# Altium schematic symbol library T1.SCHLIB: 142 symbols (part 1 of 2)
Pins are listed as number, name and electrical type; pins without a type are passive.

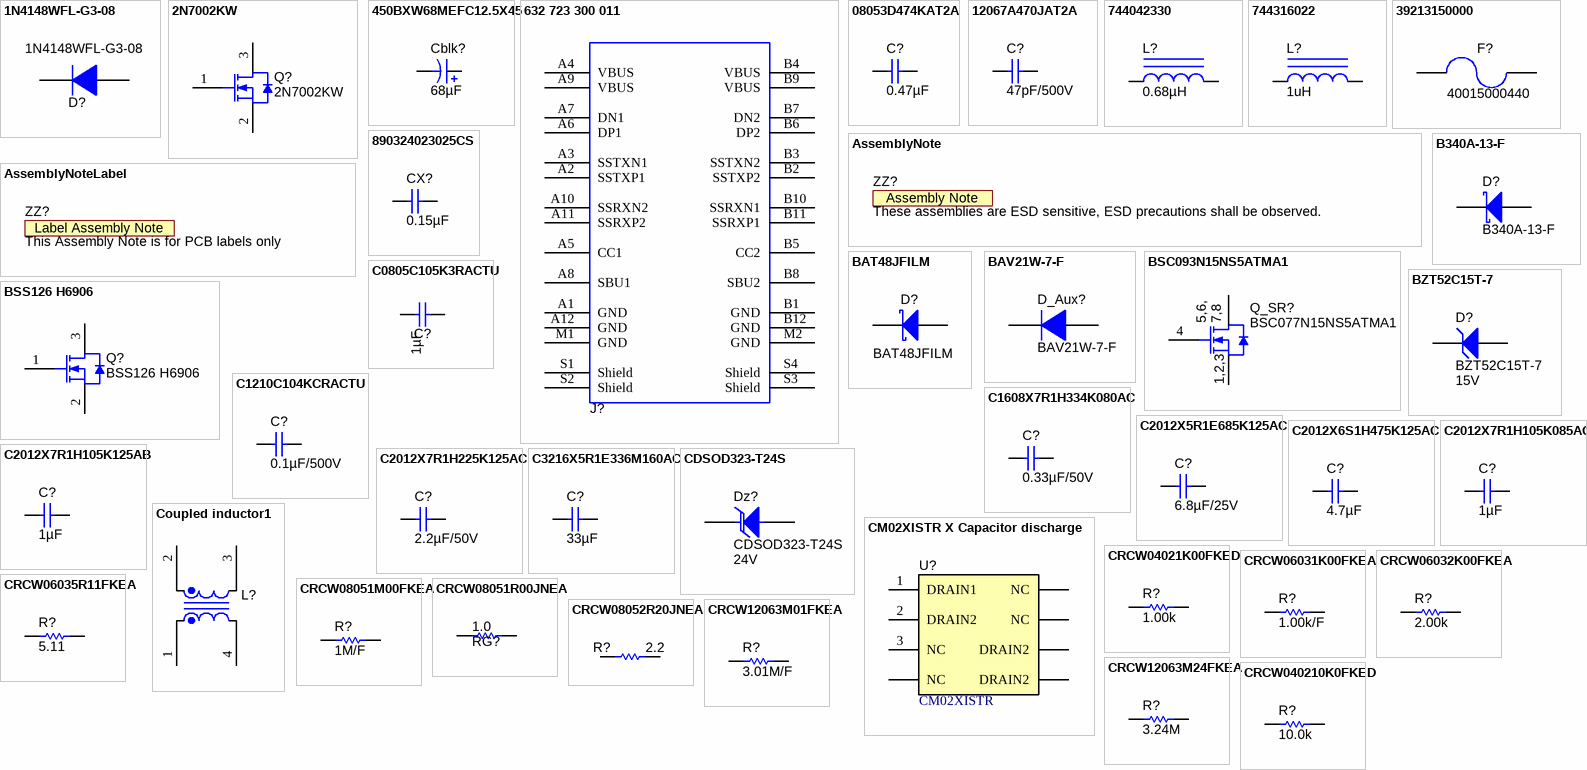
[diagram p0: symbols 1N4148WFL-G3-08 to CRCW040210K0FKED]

## 1N4148WFL-G3-08
designator D?
Diode, Switching, 100 V, 0.15 A, SOD-123FL; Manufacturer: Vishay-Semiconductor; U/M: EA; Vf_V: 1.2; Value: 100V; Value1: 0.15A; Value2: 1.2V; Io_A: 0.15; Vr_V: 100; TJmax_C: 150; SizeAreaWB_mm2: 12.19; SizeArea_mm2: 5.94; SizeX_mm: 3.6; SizeY_mm: 1.65; SizeZ_mm: 0.98; AEC Category: Q101
signal-integrity model Diode
footprint SOD-123FL
pins: 1 K, 2 A

## 2N7002KW
designator Q?
MOSFET, N-CH, 60 V, 0.31 A, SOT-323; Manufacturer: Fairchild Semiconductor; Alternate Manufacturer: None; U/M: EA; ChType: N; Value: 60V; VdsMax_V: 60; Value1: 1.6 ohm; Rdson45_ohm: 1.6; Value2: ? nC; Vgs_V: 2.1; IdsMax_A: 0.31; SizeAreaWB_mm2: 10.24; SizeArea_mm2: 4.84; SizeX_mm: 2.2; SizeZ_mm: 1.1; AEC Category: Q101
footprint SOT-323
pins: 1 G, 2 S, 3 D

## 450BXW68MEFC12.5X45
designator Cblk?  ValueDisplayed: 68µF  (hidden comment: 450BXW68MEFC12.5X45)
CAP, AL, 68 µF, 450 V, +/- 20%, TH; Manufacturer: Rubycon; Polarized: Y; CompType: Capacitor; Value: 68uF; U/M: EA; Cap_F: 0.000068; Tolerance_%: 20; Value1: Unknown; VDC_V: 450; Value2: 450V; IRMS_A: 0.61; TaMin_C: -40; TaMax_C: 105; Cap_Case: 12.5X45mm; SizeAreaWB_mm2: 210.25; SizeArea_mm2: 156.25; SizeX_mm: 12.5; SizeZ_mm: 47; AEC Category: Q200; AEC Qualified: N
signal-integrity model Cap
simulation model Cap
footprint BXW_1250x4500
footprint BXW_1250x4500_Horizontal_UP
footprint BXW_1250x4500_Horizontal_DOWN
pins: 1 +, 2 -

## 632 723 300 011
designator J?  (value not drawn)
Connector, Receptacle, USB Type C, R/A; Manufacturer: Wurth Elektronik; SymbolCreator: a0412235; Gender: Female; ContactFinish: Gold; Current_A: 3; Voltage_V: 5; Cert_UL: Y
footprint Wurth_632_723_300_011
pins: A1 GND, A2 SSTXP1, A3 SSTXN1, A4 VBUS, A5 CC1, A6 DP1, A7 DN1, A8 SBU1, A9 VBUS, A10 SSRXN2, A11 SSRXP2, A12 GND, B1 GND, B2 SSTXP2, B3 SSTXN2, B4 VBUS, B5 CC2, B6 DP2, B7 DN2, B8 SBU2, B9 VBUS, B10 SSRXN1, B11 SSRXP1, B12 GND, M1 GND, M2 GND, S1 Shield, S2 Shield, S3 Shield, S4 Shield

## 08053D474KAT2A
designator C?  ValueDisplayed: 0.47µF  (hidden comment: 08053D474KAT2A)
CAP, CERM, 0.47 µF, 25 V,+/- 10%, X5R, 0805; Manufacturer: AVX; Polarized: N; CompType: Capacitor; Value: 0.47uF; U/M: EA; Cap_F: 0.00000047; Tolerance_%: 10; ESR_ohm: 0.017; Value1: 0.017 ohm; VDC_V: 25; Value2: 25V; TaMin_C: -55; TaMax_C: 85; Cap_Case: 0805; SizeArea_mm2: 2.5; SizeAreaWB_mm2: 6.75; SizeX_mm: 2; SizeY_mm: 1.25; SizeZ_mm: 1.45; AEC Category: Q200; Green_Lifecycle: Active; Green_REACh: Passed
signal-integrity model Cap
simulation model Cap
footprint 0805_HV
footprint 0805_HV1
footprint 0805
footprint 0805M
footprint 0805L
pins: 1, 2

## 12067A470JAT2A
designator C?  ValueDisplayed: 47pF/500V  (hidden comment: 12067A470JAT2A)
CAP, CERM, 47 pF, 500 V, +/- 5%, C0G/NP0, 1206; Manufacturer: AVX; Polarized: N; CompType: Capacitor; Value: 47pF; U/M: EA; Cap_F: 0.000000000047; Tolerance_%: 5; Value1: Unknown; VDC_V: 500; Value2: 500V; TaMin_C: -55; TaMax_C: 125; Cap_Case: 1206; SizeArea_mm2: 5.12; SizeAreaWB_mm2: 10.92; SizeX_mm: 3.2; SizeY_mm: 1.6; SizeZ_mm: 1.35; AEC Category: Q200
signal-integrity model Cap
simulation model Cap
footprint 1206
footprint 1206M
footprint 1206L
pins: 1, 2

## 744042330
designator L?  ValueDisplayed: 0.68µH  (hidden comment: 744042330)
Inductor, Shielded Drum Core, Metal Composite, 33 µH, 0.5 A, 0.382 ohm, SMD; Manufacturer: Wurth Elektronik; Value: 0.68uH; Ind_H: 33.0E-6; Imax_A: 0.5; Irms: 0.72A @ 30C rise; Isat: 0.5A @ 35% inductance drop; DCR_ohm: 0.382; Value2: 0.5A; SizeAreaWB_mm2: 33.64; SizeArea_mm2: 23.04; SizeX_mm: 4.8; SizeZ_mm: 2; AEC Category: Q200
signal-integrity model Inductor
simulation model Inductor
footprint 1206L (1206 from SM-752 data)
pins: 1, 2

## 744316022
designator L?  ValueDisplayed: 1uH  (hidden comment: 744316022)
FIXED IND 1UH 11.5A 4.75 MOHM; Manufacturer: Wurth Elektronik; CompType: Inductor; Value: 220nH; Ind_H: 220.0E-9; Imax_A: 20; Irms: 20A @ 40C rise; Isat: 25A @ 30% inductance drop; DCR_ohm: 0.00125; Value1: 0.00125 ohm; Value2: 20A; SizeAreaWB_mm2: 55.48; SizeArea_mm2: 29.68; SizeX_mm: 5.6; SizeY_mm: 5.3; SizeZ_mm: 4.3; AEC Category: Q200; AEC Qualified: N
signal-integrity model Inductor
simulation model Inductor
footprint WE-HCI_5040
pins: 1, 2

## 39213150000
designator F?, comment 40015000440
Fuse, 5 A, 250VAC/VDC, TH; Manufacturer: Littelfuse; VDC_V: 250; Irating_A: 5; Green_Lifecycle: Active; Green_REACh: Passed
footprint FUSE_392
pins: 1, 2

## 890324023025CS
designator CX?  ValueDisplayed: 0.15µF  (hidden comment: 890324023025CS)
CAP, Film, 0.15 µF,  V, +/- 10%, TH; Manufacturer: Wurth Elektronik; Polarized: N; CompType: Capacitor; Value: 0.15uF; U/M: EA; Cap_F: 0.00000015; Tolerance_%: 10; Value1: Unknown; TaMin_C: -40; TaMax_C: 105; Cap_Case: 13x7x12; SizeAreaWB_mm2: 135; SizeArea_mm2: 91; SizeX_mm: 13; SizeY_mm: 7; SizeZ_mm: 12.5; AEC Category: Q200
signal-integrity model Cap
simulation model Cap
footprint WCAP-FTX2_1300x700x1200
pins: 1, 2

## AssemblyNote
designator ZZ?, comment These assemblies are ESD sensitive, ESD precautions shall be observed.  (no BOM)
SymbolCreator: codlsc; CompType: AssemblyNote
footprint AssemblyNote

## AssemblyNoteLabel
designator ZZ?, comment This Assembly Note is for PCB labels only  (no BOM)
SymbolCreator: a0412235
footprint AssemblyNoteLabel

## B340A-13-F
designator D?
Diode, Schottky, 40 V, 3 A, SMA; Manufacturer: Diodes Inc.; U/M: EA; Vf_V: 0.5; Value: 40V; Value1: 3A; Value2: 0.5V; Io_A: 3; Vr_V: 40; TJmax_C: 125; RJC_CperW: 25; SizeAreaWB_mm2: 37.3428; SizeArea_mm2: 16.3228; SizeX_mm: 5.59; SizeY_mm: 2.92; SizeZ_mm: 2.87; AEC Category: Q101
signal-integrity model Diode
simulation model DI_B340A
footprint SMA
pins: 1 K, 2 A

## BAT48JFILM
designator D?
Diode, Schottky, 30 V, 0.35 A, SOD-323; Manufacturer: STMicroelectronics; U/M: EA; Vf_V: 0.75; Value: 30V; Value1: 0.35A; Value2: 0.75V; Io_A: 0.35; Vr_V: 30; TJmax_C: 150; SizeAreaWB_mm2: 8.695; SizeArea_mm2: 3.645; SizeX_mm: 2.7; SizeY_mm: 1.35; SizeZ_mm: 1; AEC Category: Q101
signal-integrity model Diode
footprint SOD-323
pins: 1 K, 2 A

## BAV21W-7-F
designator D_Aux?
Diode, Switching, 200 V, 0.2 A, SOD-123; Manufacturer: Diodes Inc.; U/M: EA; Vf_V: 1.25; Value: 200V; Value1: 0.2A; Value2: 1.25V; Io_A: 0.2; Vr_V: 200; TJmax_C: 150; SizeAreaWB_mm2: 13.095; SizeArea_mm2: 6.545; SizeX_mm: 3.85; SizeY_mm: 1.7; SizeZ_mm: 1.35; AEC Category: Q101
signal-integrity model Diode
simulation model DI_BAV21W
footprint SOD-123
pins: 1 K, 2 A

## BSC093N15NS5ATMA1
designator Q_SR?, comment BSC077N15NS5ATMA1
MOSFET, N-CH, 150 V, 87 A, PG-TDSON-8; Manufacturer: Infineon Technologies; Alternate Manufacturer: None; U/M: EA; ChType: N; Value: 150V; VdsMax_V: 150; Value1: ? ohm; Value2: 33 nC; QgTyp_nC: 33; Vgs_V: 20; IdsMax_A: 87; SizeAreaWB_mm2: 55.131; SizeArea_mm2: 29.351; SizeX_mm: 5.99; SizeY_mm: 4.9; SizeZ_mm: 1.12; AEC Category: Q101
footprint PG-TDSON-8
pins: 1 S, 2 S, 3 S, 4 G, 5 D, 6 D, 7 D, 8 D, 9 D

## BSS126 H6906
designator Q?
MOSFET, N-CH, 600 V, 0.021 A, AEC-Q101, SOT-23; Manufacturer: Infineon Technologies; Alternate Manufacturer: None; U/M: EA; ChType: N; Value: 600V; VdsMax_V: 600; Value1: ? ohm; Value2: 1.4 nC; QgTyp_nC: 1.4; Vgs_V: 20; IdsMax_A: 0.021; SizeAreaWB_mm2: 14; SizeArea_mm2: 7.5; SizeX_mm: 2.5; SizeY_mm: 3; SizeZ_mm: 1.1; AEC Category: Q101; AEC Qualified: Y
footprint SOT-23
footprint SOT-23M
footprint SOT-23L
pins: 1 G, 2 S, 3 D

## BZT52C15T-7
designator D?  value 15V
Diode, Zener, 15 V, 300 mW, SOD-523; Manufacturer: Diodes Inc.; SymbolCreator: a0412235; U/M: EA; Power_W: 0.3; Vz_V: 15; Value1: 0.3W; RJA_CperW: 417; SizeAreaWB_mm2: 5.13; SizeArea_mm2: 1.53; SizeX_mm: 1.7; SizeY_mm: 0.9; SizeZ_mm: 0.65; AEC Category: Q101
signal-integrity model Diode
footprint SOD-523
pins: 1 K, 2 A

## C0805C105K3RACTU
designator C?  ValueDisplayed: 1µF  (hidden comment: C0805C105K3RACTU)
CAP, CERM, 1 µF, 25 V, +/- 10%, X7R, 0805; Manufacturer: Kemet; Polarized: N; CompType: Capacitor; Value: 1uF; U/M: EA; Cap_F: 0.000001; Tolerance_%: 10; Value1: Unknown; VDC_V: 25; Value2: 25V; TaMin_C: -55; TaMax_C: 125; Cap_Case: 0805; SizeArea_mm2: 2.5; SizeAreaWB_mm2: 6.75; SizeX_mm: 2; SizeY_mm: 1.25; SizeZ_mm: 1.45; AEC Category: Q200
signal-integrity model Cap
simulation model Cap
footprint 0805_HV
footprint 0805_HV1
footprint 0805
footprint 0805M
footprint 0805L
pins: 1, 2

## C1210C104KCRACTU
designator C?  ValueDisplayed: 0.1µF/500V  (hidden comment: C1210C104KCRACTU)
CAP, CERM, 0.1 µF, 500 V, +/- 10%, X7R, 1210; Manufacturer: Kemet; Polarized: N; CompType: Capacitor; Value: 0.1uF; U/M: EA; Cap_F: 0.0000001; Tolerance_%: 10; Value1: Unknown; VDC_V: 500; Value2: 500V; TaMin_C: -55; TaMax_C: 125; Cap_Case: 1210; SizeArea_mm2: 8; SizeAreaWB_mm2: 14.7; SizeX_mm: 3.2; SizeY_mm: 2.5; SizeZ_mm: 2.3; AEC Category: Q200
signal-integrity model Cap
simulation model Cap
footprint 1210_230
footprint 1210_230M
footprint 1210_230L
pins: 1, 2

## C1608X7R1H334K080AC
designator C?  ValueDisplayed: 0.33µF/50V  (hidden comment: C1608X7R1H334K080AC)
CAP, CERM, 0.33 µF, 50 V, +/- 10%, X7R, 0603; Manufacturer: TDK; Polarized: N; CompType: Capacitor; Value: 0.33uF; U/M: EA; Cap_F: 0.00000033; Tolerance_%: 10; ESR_ohm: 0.016574; Value1: 0.016574 ohm; VDC_V: 50; Value2: 50V; IRMS_A: 1.28367; TaMin_C: -55; TaMax_C: 125; Cap_Case: 0603; SizeArea_mm2: 1.28; SizeAreaWB_mm2: 4.68; SizeX_mm: 1.6; SizeY_mm: 0.8; SizeZ_mm: 1; AEC Category: Q200
signal-integrity model Cap
simulation model Cap
footprint 0603
footprint 0603M
footprint 0603L
footprint 0603_HV
footprint 0603S
pins: 1, 2

## C2012X5R1E685K125AC
designator C?  ValueDisplayed: 6.8µF/25V  (hidden comment: C2012X5R1E685K125AC)
CAP, CERM, 6.8 µF, 25 V, +/- 10%, X5R, 0805; Manufacturer: TDK; Polarized: N; CompType: Capacitor; Value: 6.8uF; U/M: EA; Cap_F: 0.0000068; Tolerance_%: 10; Value1: Unknown; VDC_V: 25; Value2: 25V; TaMin_C: -55; TaMax_C: 85; Cap_Case: 0805; SizeArea_mm2: 2.5; SizeAreaWB_mm2: 6.75; SizeX_mm: 2; SizeY_mm: 1.25; SizeZ_mm: 1.45; AEC Category: Q200
signal-integrity model Cap
simulation model Cap
footprint 0805_HV
footprint 0805_HV1
footprint 0805
footprint 0805M
footprint 0805L
pins: 1, 2

## C2012X6S1H475K125AC
designator C?  ValueDisplayed: 4.7µF  (hidden comment: C2012X6S1H475K125AC)
CAP, CERM, 4.7 µF, 50 V, +/- 10%, X6S, 0805; Manufacturer: TDK; Polarized: N; CompType: Capacitor; Value: 4.7uF; U/M: EA; Cap_F: 0.0000047; Tolerance_%: 10; ESR_ohm: 0.002346; Value1: 0.002346 ohm; VDC_V: 50; Value2: 50V; IRMS_A: 4.26021; TaMin_C: -55; TaMax_C: 105; Cap_Case: 0805; SizeArea_mm2: 2.5; SizeAreaWB_mm2: 6.75; SizeX_mm: 2; SizeY_mm: 1.25; SizeZ_mm: 1.45; AEC Category: Q200
signal-integrity model Cap
simulation model Cap
footprint 0805_HV
footprint 0805_HV1
footprint 0805
footprint 0805M
footprint 0805L
pins: 1, 2

## C2012X7R1H105K085AC
designator C?  ValueDisplayed: 1µF  (hidden comment: C2012X7R1H105K085AC)
CAP, CERM, 1 µF, 50 V, +/- 10%, X7R, 0805; Manufacturer: TDK; Polarized: N; CompType: Capacitor; Value: 1uF; U/M: EA; Cap_F: 0.000001; Tolerance_%: 10; Value1: Unknown; VDC_V: 50; Value2: 50V; TaMin_C: -55; TaMax_C: 125; Cap_Case: 0805; SizeArea_mm2: 2.5; SizeAreaWB_mm2: 6.75; SizeX_mm: 2; SizeY_mm: 1.25; SizeZ_mm: 1.45; AEC Category: Q200
signal-integrity model Cap
simulation model Cap
footprint 0805_HV
footprint 0805_HV1
footprint 0805
footprint 0805M
footprint 0805L
pins: 1, 2

## C2012X7R1H105K125AB
designator C?  ValueDisplayed: 1µF  (hidden comment: C2012X7R1H105K125AB)
CAP, CERM, 1 µF, 50 V, +/- 10%, X7R, 0805; Manufacturer: TDK; Polarized: N; CompType: Capacitor; Value: 1uF; U/M: EA; Cap_F: 0.000001; Tolerance_%: 10; ESR_ohm: 0.008782; Value1: 0.008782 ohm; VDC_V: 50; Value2: 50V; IRMS_A: 2.20488; TaMin_C: -55; TaMax_C: 125; Cap_Case: 0805; SizeArea_mm2: 2.5; SizeAreaWB_mm2: 6.75; SizeX_mm: 2; SizeY_mm: 1.25; SizeZ_mm: 1.45; AEC Category: Q200
signal-integrity model Cap
simulation model Cap
footprint 0805_HV
footprint 0805_HV1
footprint 0805
footprint 0805M
footprint 0805L
pins: 1, 2

## C2012X7R1H225K125AC
designator C?  ValueDisplayed: 2.2µF/50V  (hidden comment: C2012X7R1H225K125AC)
CAP, CERM, 2.2 µF, 50 V, +/- 10%, X7R, 0805; Manufacturer: TDK; Polarized: N; CompType: Capacitor; Value: 2.2uF; U/M: EA; Cap_F: 0.0000022; Tolerance_%: 10; ESR_ohm: 0.00366; Value1: 0.00366 ohm; VDC_V: 50; Value2: 50V; IRMS_A: 3.41207; TaMin_C: -55; TaMax_C: 125; Cap_Case: 0805; SizeArea_mm2: 2.5; SizeAreaWB_mm2: 6.75; SizeX_mm: 2; SizeY_mm: 1.25; SizeZ_mm: 1.45; AEC Category: Q200
signal-integrity model Cap
simulation model Cap
footprint 0805_HV
footprint 0805_HV1
footprint 0805
footprint 0805M
footprint 0805L
pins: 1, 2

## C3216X5R1E336M160AC
designator C?  ValueDisplayed: 33µF  (hidden comment: C3216X5R1E336M160AC)
CAP, CERM, 33 µF, 25 V, +/- 20%, X5R, 1206; Manufacturer: TDK; Polarized: N; CompType: Capacitor; Value: 33uF; U/M: EA; Cap_F: 0.000033; Tolerance_%: 20; ESR_ohm: 0.002648; Value1: 0.002648 ohm; VDC_V: 25; Value2: 25V; IRMS_A: 4.45864; TaMin_C: -55; TaMax_C: 85; Cap_Case: 1206_180; SizeArea_mm2: 5.12; SizeAreaWB_mm2: 10.92; SizeX_mm: 3.2; SizeY_mm: 1.6; SizeZ_mm: 1.8; AEC Category: Q200
signal-integrity model Cap
simulation model Cap
footprint 1206_180
footprint 1206_180M
footprint 1206_180L
pins: 1, 2

## CDSOD323-T24S
designator Dz?  value 24V
Diode, TVS, Uni, 24 V, 49 Vc, SOD-323; Manufacturer: Bourns; U/M: EA; Vr_V: 24; Value1: W; SizeAreaWB_mm2: 8.695; SizeArea_mm2: 3.645; SizeX_mm: 2.7; SizeY_mm: 1.35; SizeZ_mm: 1; AEC Category: Q101; AEC Qualified: N
footprint SOD-323
pins: 1 K, 2 A

## CM02XISTR X Capacitor discharge
designator U?, comment CM02XISTR
1.25 V, 50 ppm / degC, 50 uA Series (Bandgap) Voltage Reference, -40 to 125 degC, 3-pin SOT-23 (DBZ), Green (RoHS & no Sb/Br); Manufacturer: Champion; Alternate Manufacturer: Texas Instruments; Alternate PartNumber: Equivalent; Initial Accuracy @ 25/deg C(%): 0.2; Iq(Max)(uA): 50; Rating: Catalog; SubFamily: Series Voltage Reference; Temp Coeff(Typ)(ppm/ degree C): 20; VI(Max)(V): 5.5; VI(Min)(V): 1.8; VO(V): 1.25
footprint SOP8 (SOIC, 8-Leads, Body 4.9x3.9mm, Pitch 1.27mm, IPC Medium Density)
pins: 1 DRAIN1 (power), 2 DRAIN2 (power), 3 NC (power), 4 NC, 5 DRAIN2, 6 DRAIN2, 7 NC, 8 NC

## Coupled inductor1
designator L?, comment 7448011305  (value not drawn)
Coupled inductor, 5 mH, 1.3 A, 0.2 ohm, TH; Manufacturer: Wurth Elektronik; SymbolCreator: a0799628; Value: 5mH; Ind_H: 5.0E-3; DCR_ohm: 0.2
footprint WE-CMBNC_XS (TH, 4-Leads, Body 14x7.5mm)
pins: 1, 2, 3, 4
1 alternate drawing of the same symbol

## CRCW04021K00FKED
designator R?  ValueDisplayed: 1.00k  (hidden comment: CRCW04021K00FKED)
RES, 1.00 k, 1%, 0.063 W, 0402; Manufacturer: Vishay-Dale; CompType: Resistor; Value: 1.00k; Res_ohm: 1000; Value_Code: 1k00; Tolerance_%: 1; Power_W: 0.063; Value2: 0.063W; VDC_V: 50; TempCo: 100 ppm/C; SizeArea_mm2: 0.5; SizeZ_mm: 0.6; EIA_Code: E96; U/M: EA; AEC Category: Q200
signal-integrity model Resistor
simulation model Resistor
footprint 0402
footprint 0402M
footprint 0402L
footprint 0402S
pins: 1, 2

## CRCW06031K00FKEA
designator R?  ValueDisplayed: 1.00k/F  (hidden comment: CRCW06031K00FKEA)
RES, 1.00 k, 1%, 0.1 W, 0603; Manufacturer: Vishay-Dale; CompType: Resistor; Value: 1.00k; Res_ohm: 1000; Value_Code: 1k00; Tolerance_%: 1; Power_W: 0.1; Value2: 0.1W; VDC_V: 75; TempCo: 100 ppm/C; SizeArea_mm2: 1.28; SizeX_mm: 1.6; SizeY_mm: 0.8; EIA_Code: E96; U/M: EA; AEC Category: Q200
signal-integrity model Resistor
simulation model Resistor
footprint 0603
footprint 0603M
footprint 0603L
footprint 0603_HV
footprint 0603S
pins: 1, 2

## CRCW06032K00FKEA
designator R?  ValueDisplayed: 2.00k  (hidden comment: CRCW06032K00FKEA)
RES, 2.00 k, 1%, 0.1 W, 0603; Manufacturer: Vishay-Dale; CompType: Resistor; Value: 2.00k; Res_ohm: 2000; Value_Code: 2k00; Tolerance_%: 1; Power_W: 0.1; Value2: 0.1W; VDC_V: 75; TempCo: 100 ppm/C; SizeArea_mm2: 1.28; SizeX_mm: 1.6; SizeY_mm: 0.8; EIA_Code: E96; U/M: EA; AEC Category: Q200
signal-integrity model Resistor
simulation model Resistor
footprint 0603
footprint 0603M
footprint 0603L
footprint 0603_HV
footprint 0603S
pins: 1, 2

## CRCW06035R11FKEA
designator R?  ValueDisplayed: 5.11  (hidden comment: CRCW06035R11FKEA)
RES, 5.11, 1%, 0.1 W, 0603; Manufacturer: Vishay-Dale; CompType: Resistor; Value: 5.11; Value_Code: 5R11; Tolerance_%: 1; Power_W: 0.1; Value2: 0.1W; VDC_V: 75; TempCo: 100 ppm/C; SizeArea_mm2: 1.28; SizeX_mm: 1.6; SizeY_mm: 0.8; EIA_Code: E96; U/M: EA; AEC Category: Q200
signal-integrity model Resistor
simulation model Resistor
footprint 0603
footprint 0603M
footprint 0603L
footprint 0603_HV
footprint 0603S
pins: 1, 2

## CRCW08051M00FKEA
designator R?  ValueDisplayed: 1M/F  (hidden comment: CRCW08051M00FKEA)
RES, 1.00 M, 1%, 0.125 W, 0805; Manufacturer: Vishay-Dale; CompType: Resistor; Value: 1.00Meg; Res_ohm: 1000000; Value_Code: 1M00; Tolerance_%: 1; Power_W: 0.125; Value2: 0.125W; VDC_V: 150; TempCo: 100 ppm/C; SizeArea_mm2: 2.5; SizeX_mm: 2; SizeY_mm: 1.25; SizeZ_mm: 1.45; EIA_Code: E96; U/M: EA; AEC Category: Q200
signal-integrity model Resistor
simulation model Resistor
footprint 0805_HV
footprint 0805_HV1
footprint 0805
footprint 0805M
footprint 0805L
pins: 1, 2

## CRCW08051R00JNEA
designator RG?  ValueDisplayed: 1.0  (hidden comment: CRCW08051R00JNEA)
RES, 1.0, 5%, 0.125 W, 0805; Manufacturer: Vishay-Dale; CompType: Resistor; Value: 1.0; Res_ohm: 1; Value_Code: 1R00; Tolerance_%: 5; Power_W: 0.125; Value2: 0.125W; VDC_V: 150; TempCo: 200 ppm/C; SizeArea_mm2: 2.5; SizeX_mm: 2; SizeY_mm: 1.25; SizeZ_mm: 1.45; EIA_Code: E24; U/M: EA; AEC Category: Q200
signal-integrity model Resistor
simulation model Resistor
footprint 0805_HV
footprint 0805_HV1
footprint 0805
footprint 0805M
footprint 0805L
pins: 1, 2

## CRCW08052R20JNEA
designator R?  ValueDisplayed: 2.2  (hidden comment: CRCW08052R20JNEA)
RES, 2.2, 5%, 0.125 W, 0805; Manufacturer: Vishay-Dale; CompType: Resistor; Value: 2.2; Value_Code: 2R20; Tolerance_%: 5; Power_W: 0.125; Value2: 0.125W; VDC_V: 150; TempCo: 200 ppm/C; SizeArea_mm2: 2.5; SizeX_mm: 2; SizeY_mm: 1.25; SizeZ_mm: 1.45; EIA_Code: E24; U/M: EA; AEC Category: Q200; Green_Lifecycle: Active; Green_REACh: Passed
signal-integrity model Resistor
simulation model Resistor
footprint 0805_HV
footprint 0805_HV1
footprint 0805
footprint 0805M
footprint 0805L
pins: 1, 2

## CRCW12063M01FKEA
designator R?  ValueDisplayed: 3.01M/F  (hidden comment: CRCW12063M01FKEA)
RES, 3.01 M, 1%, 0.25 W, 1206; Manufacturer: Vishay-Dale; CompType: Resistor; Value: 3.01Meg; Res_ohm: 3010000; Value_Code: 3M01; Tolerance_%: 1; Power_W: 0.25; Value2: 0.25W; VDC_V: 200; TempCo: 100 ppm/C; SizeArea_mm2: 5.12; SizeX_mm: 3.2; SizeY_mm: 1.6; SizeZ_mm: 1.35; EIA_Code: E96; U/M: EA; AEC Category: Q200
signal-integrity model Resistor
simulation model Resistor
footprint 1206
footprint 1206M
footprint 1206L
pins: 1, 2

## CRCW12063M24FKEA
designator R?  ValueDisplayed: 3.24M  (hidden comment: CRCW12063M24FKEA)
RES, 3.24 M, 1%, 0.25 W, 1206; Manufacturer: Vishay-Dale; CompType: Resistor; Value: 3.24Meg; Res_ohm: 3240000; Value_Code: 3M24; Tolerance_%: 1; Power_W: 0.25; Value2: 0.25W; VDC_V: 200; TempCo: 100 ppm/C; SizeArea_mm2: 5.12; SizeX_mm: 3.2; SizeY_mm: 1.6; SizeZ_mm: 1.35; EIA_Code: E96; U/M: EA; AEC Category: Q200
signal-integrity model Resistor
simulation model Resistor
footprint 1206
footprint 1206M
footprint 1206L
pins: 1, 2

## CRCW040210K0FKED
designator R?  ValueDisplayed: 10.0k  (hidden comment: CRCW040210K0FKED)
RES, 10.0 k, 1%, 0.063 W, 0402; Manufacturer: Vishay-Dale; CompType: Resistor; Value: 10.0k; Res_ohm: 10000; Value_Code: 10k0; Tolerance_%: 1; Power_W: 0.063; Value2: 0.063W; VDC_V: 50; TempCo: 100 ppm/C; SizeArea_mm2: 0.5; SizeZ_mm: 0.6; EIA_Code: E96; U/M: EA; AEC Category: Q200
signal-integrity model Resistor
simulation model Resistor
footprint 0402
footprint 0402M
footprint 0402L
footprint 0402S
pins: 1, 2

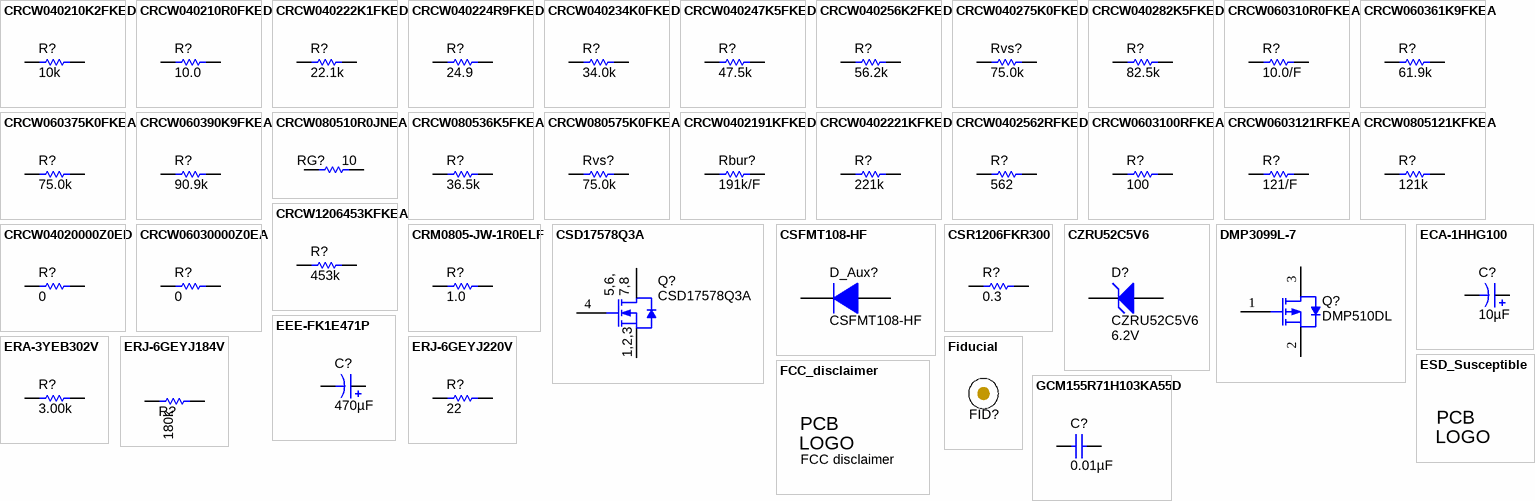
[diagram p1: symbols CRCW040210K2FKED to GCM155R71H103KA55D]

## CRCW040210K2FKED
designator R?  ValueDisplayed: 10k  (hidden comment: CRCW040210K2FKED)
RES, 10 k, 1%, 0.063 W, 0402; Manufacturer: Vishay-Dale; CompType: Resistor; Value: 10k; Res_ohm: 10200; Tolerance_%: 1; Power_W: 0.063; Value2: 0.063W; VDC_V: 50; TempCo: 100 ppm/C; SizeArea_mm2: 0.5; SizeZ_mm: 0.6; EIA_Code: E96; U/M: EA; AEC Category: Q200
signal-integrity model Resistor
simulation model Resistor
footprint 0402
footprint 0402M
footprint 0402L
footprint 0402S
pins: 1, 2

## CRCW040210R0FKED
designator R?  ValueDisplayed: 10.0  (hidden comment: CRCW040210R0FKED)
RES, 10.0, 1%, 0.063 W, 0402; Manufacturer: Vishay-Dale; CompType: Resistor; Value: 10.0; Res_ohm: 10; Value_Code: 10R0; Tolerance_%: 1; Power_W: 0.063; Value2: 0.063W; VDC_V: 50; TempCo: 100 ppm/C; SizeArea_mm2: 0.5; SizeZ_mm: 0.6; EIA_Code: E96; U/M: EA; AEC Category: Q200
signal-integrity model Resistor
simulation model Resistor
footprint 0402
footprint 0402M
footprint 0402L
footprint 0402S
pins: 1, 2

## CRCW040222K1FKED
designator R?  ValueDisplayed: 22.1k  (hidden comment: CRCW040222K1FKED)
RES, 22.1 k, 1%, 0.063 W, 0402; Manufacturer: Vishay-Dale; CompType: Resistor; Value: 22.1k; Res_ohm: 22100; Value_Code: 22k1; Tolerance_%: 1; Power_W: 0.063; Value2: 0.063W; VDC_V: 50; TempCo: 100 ppm/C; SizeArea_mm2: 0.5; SizeZ_mm: 0.6; EIA_Code: E96; U/M: EA; AEC Category: Q200
signal-integrity model Resistor
simulation model Resistor
footprint 0402
footprint 0402M
footprint 0402L
footprint 0402S
pins: 1, 2

## CRCW040224R9FKED
designator R?  ValueDisplayed: 24.9  (hidden comment: CRCW040224R9FKED)
RES, 24.9, 1%, 0.063 W, 0402; Manufacturer: Vishay-Dale; CompType: Resistor; Value: 24.9; Value_Code: 24R9; Tolerance_%: 1; Power_W: 0.063; Value2: 0.063W; VDC_V: 50; TempCo: 100 ppm/C; SizeArea_mm2: 0.5; SizeZ_mm: 0.6; EIA_Code: E96; U/M: EA; AEC Category: Q200
signal-integrity model Resistor
simulation model Resistor
footprint 0402
footprint 0402M
footprint 0402L
footprint 0402S
pins: 1, 2

## CRCW040234K0FKED
designator R?  ValueDisplayed: 34.0k  (hidden comment: CRCW040234K0FKED)
RES, 34.0 k, 1%, 0.063 W, 0402; Manufacturer: Vishay-Dale; CompType: Resistor; Value: 34.0k; Res_ohm: 34000; Value_Code: 34k0; Tolerance_%: 1; Power_W: 0.063; Value2: 0.063W; VDC_V: 50; TempCo: 100 ppm/C; SizeArea_mm2: 0.5; SizeZ_mm: 0.6; EIA_Code: E96; U/M: EA; AEC Category: Q200
signal-integrity model Resistor
simulation model Resistor
footprint 0402
footprint 0402M
footprint 0402L
footprint 0402S
pins: 1, 2

## CRCW040247K5FKED
designator R?  ValueDisplayed: 47.5k  (hidden comment: CRCW040247K5FKED)
RES, 47.5 k, 1%, 0.063 W, 0402; Manufacturer: Vishay-Dale; CompType: Resistor; Value: 47.5k; Res_ohm: 47500; Value_Code: 47k5; Tolerance_%: 1; Power_W: 0.063; Value2: 0.063W; VDC_V: 50; TempCo: 100 ppm/C; SizeArea_mm2: 0.5; SizeZ_mm: 0.6; EIA_Code: E96; U/M: EA; AEC Category: Q200
signal-integrity model Resistor
simulation model Resistor
footprint 0402
footprint 0402M
footprint 0402L
footprint 0402S
pins: 1, 2

## CRCW040256K2FKED
designator R?  ValueDisplayed: 56.2k  (hidden comment: CRCW040256K2FKED)
RES, 56.2 k, 1%, 0.063 W, 0402; Manufacturer: Vishay-Dale; CompType: Resistor; Value: 56.2k; Res_ohm: 56200; Value_Code: 56k2; Tolerance_%: 1; Power_W: 0.063; Value2: 0.063W; VDC_V: 50; TempCo: 100 ppm/C; SizeArea_mm2: 0.5; SizeZ_mm: 0.6; EIA_Code: E96; U/M: EA; AEC Category: Q200
signal-integrity model Resistor
simulation model Resistor
footprint 0402
footprint 0402M
footprint 0402L
footprint 0402S
pins: 1, 2

## CRCW040275K0FKED
designator Rvs?  ValueDisplayed: 75.0k  (hidden comment: CRCW040275K0FKED)
RES, 75.0 k, 1%, 0.063 W, 0402; Manufacturer: Vishay-Dale; CompType: Resistor; Value: 75.0k; Res_ohm: 75000; Value_Code: 75k0; Tolerance_%: 1; Power_W: 0.063; Value2: 0.063W; VDC_V: 50; TempCo: 100 ppm/C; SizeArea_mm2: 0.5; SizeZ_mm: 0.6; EIA_Code: E96; U/M: EA; AEC Category: Q200
signal-integrity model Resistor
simulation model Resistor
footprint 0402
footprint 0402M
footprint 0402L
footprint 0402S
pins: 1, 2

## CRCW040282K5FKED
designator R?  ValueDisplayed: 82.5k  (hidden comment: CRCW040282K5FKED)
RES, 82.5 k, 1%, 0.063 W, 0402; Manufacturer: Vishay-Dale; CompType: Resistor; Value: 82.5k; Res_ohm: 82500; Value_Code: 82k5; Tolerance_%: 1; Power_W: 0.063; Value2: 0.063W; VDC_V: 50; TempCo: 100 ppm/C; SizeArea_mm2: 0.5; SizeZ_mm: 0.6; EIA_Code: E96; U/M: EA; AEC Category: Q200
signal-integrity model Resistor
simulation model Resistor
footprint 0402
footprint 0402M
footprint 0402L
footprint 0402S
pins: 1, 2

## CRCW060310R0FKEA
designator R?  ValueDisplayed: 10.0/F  (hidden comment: CRCW060310R0FKEA)
RES, 10.0, 1%, 0.1 W, 0603; Manufacturer: Vishay-Dale; CompType: Resistor; Value: 10.0; Res_ohm: 10; Value_Code: 10R0; Tolerance_%: 1; Power_W: 0.1; Value2: 0.1W; VDC_V: 75; TempCo: 100 ppm/C; SizeArea_mm2: 1.28; SizeX_mm: 1.6; SizeY_mm: 0.8; EIA_Code: E96; U/M: EA; AEC Category: Q200
signal-integrity model Resistor
simulation model Resistor
footprint 0603
footprint 0603M
footprint 0603L
footprint 0603_HV
footprint 0603S
pins: 1, 2

## CRCW060361K9FKEA
designator R?  ValueDisplayed: 61.9k  (hidden comment: CRCW060361K9FKEA)
RES, 61.9 k, 1%, 0.1 W, 0603; Manufacturer: Vishay-Dale; CompType: Resistor; Value: 61.9k; Res_ohm: 61900; Value_Code: 61k9; Tolerance_%: 1; Power_W: 0.1; Value2: 0.1W; VDC_V: 75; TempCo: 100 ppm/C; SizeArea_mm2: 1.28; SizeX_mm: 1.6; SizeY_mm: 0.8; EIA_Code: E96; U/M: EA; AEC Category: Q200; Green_Lifecycle: Active; Green_REACh: Passed
signal-integrity model Resistor
simulation model Resistor
footprint 0603 (0603 from SM-752 data)
footprint 0603M
footprint 0603L
footprint 0603_HV
footprint 0603S
pins: 1, 2

## CRCW060375K0FKEA
designator R?  ValueDisplayed: 75.0k  (hidden comment: CRCW060375K0FKEA)
RES, 75.0 k, 1%, 0.1 W, 0603; Manufacturer: Vishay-Dale; CompType: Resistor; Value: 75.0k; Res_ohm: 75000; Value_Code: 75k0; Tolerance_%: 1; Power_W: 0.1; Value2: 0.1W; VDC_V: 75; TempCo: 100 ppm/C; SizeArea_mm2: 1.28; SizeX_mm: 1.6; SizeY_mm: 0.8; EIA_Code: E96; U/M: EA; AEC Category: Q200
signal-integrity model Resistor
simulation model Resistor
footprint 0603
footprint 0603M
footprint 0603L
footprint 0603_HV
footprint 0603S
pins: 1, 2

## CRCW060390K9FKEA
designator R?  ValueDisplayed: 90.9k  (hidden comment: CRCW060390K9FKEA)
RES, 90.9 k, 1%, 0.1 W, 0603; Manufacturer: Vishay-Dale; CompType: Resistor; Value: 90.9k; Res_ohm: 90900; Value_Code: 90k9; Tolerance_%: 1; Power_W: 0.1; Value2: 0.1W; VDC_V: 75; TempCo: 100 ppm/C; SizeArea_mm2: 1.28; SizeX_mm: 1.6; SizeY_mm: 0.8; EIA_Code: E96; U/M: EA; AEC Category: Q200
signal-integrity model Resistor
simulation model Resistor
footprint 0603
footprint 0603M
footprint 0603L
footprint 0603_HV
footprint 0603S
pins: 1, 2

## CRCW080510R0JNEA
designator RG?  ValueDisplayed: 10  (hidden comment: CRCW080510R0JNEA)
RES, 10, 5%, 0.125 W, 0805; Manufacturer: Vishay-Dale; CompType: Resistor; Value: 10; Value_Code: 10R0; Tolerance_%: 5; Power_W: 0.125; Value2: 0.125W; VDC_V: 150; TempCo: 200 ppm/C; SizeArea_mm2: 2.5; SizeX_mm: 2; SizeY_mm: 1.25; SizeZ_mm: 1.45; EIA_Code: E24; U/M: EA; AEC Category: Q200
signal-integrity model Resistor
simulation model Resistor
footprint 0805_HV
footprint 0805_HV1
footprint 0805
footprint 0805M
footprint 0805L
pins: 1, 2

## CRCW080536K5FKEA
designator R?  ValueDisplayed: 36.5k  (hidden comment: CRCW080536K5FKEA)
RES, 36.5 k, 1%, 0.125 W, 0805; Manufacturer: Vishay-Dale; CompType: Resistor; Value: 36.5k; Res_ohm: 36500; Value_Code: 36k5; Tolerance_%: 1; Power_W: 0.125; Value2: 0.125W; VDC_V: 150; TempCo: 100 ppm/C; SizeArea_mm2: 2.5; SizeX_mm: 2; SizeY_mm: 1.25; SizeZ_mm: 1.45; EIA_Code: E96; U/M: EA; AEC Category: Q200; Green_Lifecycle: Active; Green_REACh: Passed
signal-integrity model Resistor
simulation model Resistor
footprint 0805_HV
footprint 0805_HV1
footprint 0805
footprint 0805M
footprint 0805L
pins: 1, 2

## CRCW080575K0FKEA
designator Rvs?  ValueDisplayed: 75.0k  (hidden comment: CRCW080575K0FKEA)
RES, 75.0 k, 1%, 0.125 W, 0805; Manufacturer: Vishay-Dale; CompType: Resistor; Value: 75.0k; Res_ohm: 75000; Value_Code: 75k0; Tolerance_%: 1; Power_W: 0.125; Value2: 0.125W; VDC_V: 150; TempCo: 100 ppm/C; SizeArea_mm2: 2.5; SizeX_mm: 2; SizeY_mm: 1.25; SizeZ_mm: 1.45; EIA_Code: E96; U/M: EA; AEC Category: Q200
signal-integrity model Resistor
simulation model Resistor
footprint 0805_HV
footprint 0805_HV1
footprint 0805
footprint 0805M
footprint 0805L
pins: 1, 2

## CRCW0402191KFKED
designator Rbur?  ValueDisplayed: 191k/F  (hidden comment: CRCW0402191KFKED)
RES, 191 k, 1%, 0.063 W, 0402; Manufacturer: Vishay-Dale; CompType: Resistor; Value: 191k; Res_ohm: 191000; Tolerance_%: 1; Power_W: 0.063; Value2: 0.063W; VDC_V: 50; TempCo: 100 ppm/C; SizeArea_mm2: 0.5; SizeZ_mm: 0.6; EIA_Code: E96; U/M: EA; AEC Category: Q200
signal-integrity model Resistor
simulation model Resistor
footprint 0402
footprint 0402M
footprint 0402L
footprint 0402S
pins: 1, 2

## CRCW0402221KFKED
designator R?  ValueDisplayed: 221k  (hidden comment: CRCW0402221KFKED)
RES, 221 k, 1%, 0.063 W, 0402; Manufacturer: Vishay-Dale; CompType: Resistor; Value: 221k; Res_ohm: 221000; Tolerance_%: 1; Power_W: 0.063; Value2: 0.063W; VDC_V: 50; TempCo: 100 ppm/C; SizeArea_mm2: 0.5; SizeZ_mm: 0.6; EIA_Code: E96; U/M: EA; AEC Category: Q200
signal-integrity model Resistor
simulation model Resistor
footprint 0402
footprint 0402M
footprint 0402L
footprint 0402S
pins: 1, 2

## CRCW0402562RFKED
designator R?  ValueDisplayed: 562  (hidden comment: CRCW0402562RFKED)
RES, 562, 1%, 0.063 W, 0402; Manufacturer: Vishay-Dale; CompType: Resistor; Value: 562; Value_Code: 562R; Tolerance_%: 1; Power_W: 0.063; Value2: 0.063W; VDC_V: 50; TempCo: 100 ppm/C; SizeArea_mm2: 0.5; SizeZ_mm: 0.6; EIA_Code: E96; U/M: EA; AEC Category: Q200
signal-integrity model Resistor
simulation model Resistor
footprint 0402
footprint 0402M
footprint 0402L
footprint 0402S
pins: 1, 2

## CRCW0603100RFKEA
designator R?  ValueDisplayed: 100  (hidden comment: CRCW0603100RFKEA)
RES, 100, 1%, 0.1 W, 0603; Manufacturer: Vishay-Dale; CompType: Resistor; Value: 100; Value_Code: 100R; Tolerance_%: 1; Power_W: 0.1; Value2: 0.1W; VDC_V: 75; TempCo: 100 ppm/C; SizeArea_mm2: 1.28; SizeX_mm: 1.6; SizeY_mm: 0.8; EIA_Code: E96; U/M: EA; AEC Category: Q200
signal-integrity model Resistor
simulation model Resistor
footprint 0603
footprint 0603M
footprint 0603L
footprint 0603_HV
footprint 0603S
pins: 1, 2

## CRCW0603121RFKEA
designator R?  ValueDisplayed: 121/F  (hidden comment: CRCW0603121RFKEA)
RES, 121, 1%, 0.1 W, 0603; Manufacturer: Vishay-Dale; CompType: Resistor; Value: 121; Value_Code: 121R; Tolerance_%: 1; Power_W: 0.1; Value2: 0.1W; VDC_V: 75; TempCo: 100 ppm/C; SizeArea_mm2: 1.28; SizeX_mm: 1.6; SizeY_mm: 0.8; EIA_Code: E96; U/M: EA; AEC Category: Q200
signal-integrity model Resistor
simulation model Resistor
footprint 0603
footprint 0603M
footprint 0603L
footprint 0603_HV
footprint 0603S
pins: 1, 2

## CRCW0805121KFKEA
designator R?  ValueDisplayed: 121k  (hidden comment: CRCW0805121KFKEA)
RES, 121 k, 1%, 0.125 W, 0805; Manufacturer: Vishay-Dale; CompType: Resistor; Value: 121k; Res_ohm: 121000; Tolerance_%: 1; Power_W: 0.125; Value2: 0.125W; VDC_V: 150; TempCo: 100 ppm/C; SizeArea_mm2: 2.5; SizeX_mm: 2; SizeY_mm: 1.25; SizeZ_mm: 1.45; EIA_Code: E96; U/M: EA; AEC Category: Q200; Green_Lifecycle: Active; Green_REACh: Passed
signal-integrity model Resistor
simulation model Resistor
footprint 0805_HV
footprint 0805_HV1
footprint 0805
footprint 0805M
footprint 0805L
pins: 1, 2

## CRCW1206453KFKEA
designator R?  ValueDisplayed: 453k  (hidden comment: CRCW1206453KFKEA)
RES, 453 k, 1%, 0.25 W, 1206; Manufacturer: Vishay-Dale; CompType: Resistor; Value: 453k; Res_ohm: 453000; Tolerance_%: 1; Power_W: 0.25; Value2: 0.25W; VDC_V: 200; TempCo: 100 ppm/C; SizeArea_mm2: 5.12; SizeX_mm: 3.2; SizeY_mm: 1.6; SizeZ_mm: 1.35; EIA_Code: E96; U/M: EA; AEC Category: Q200
signal-integrity model Resistor
simulation model Resistor
footprint 1206
footprint 1206M
footprint 1206L
pins: 1, 2

## CRCW04020000Z0ED
designator R?  ValueDisplayed: 0  (hidden comment: CRCW04020000Z0ED)
RES, 0, 5%, 0.063 W, 0402; Manufacturer: Vishay-Dale; CompType: Resistor; Value: 0; Value_Code: 0000; Tolerance_%: 5; Power_W: 0.063; Value2: 0.063W; VDC_V: 50; TempCo: 200 ppm/C; SizeArea_mm2: 0.5; SizeX_mm: 1; SizeZ_mm: 0.6; EIA_Code: E24; U/M: EA; AEC Category: Q200
signal-integrity model Resistor
simulation model Resistor
footprint 0402
footprint 0402M
footprint 0402L
footprint 0402S
pins: 1, 2

## CRCW06030000Z0EA
designator R?  ValueDisplayed: 0  (hidden comment: CRCW06030000Z0EA)
RES, 0, 5%, 0.1 W, 0603; Manufacturer: Vishay-Dale; CompType: Resistor; Value: 0; Value_Code: 0000; Tolerance_%: 5; Power_W: 0.1; Value2: 0.1W; VDC_V: 75; TempCo: 200 ppm/C; SizeArea_mm2: 1.28; SizeX_mm: 1.6; SizeY_mm: 0.8; SizeZ_mm: 1; EIA_Code: E24; U/M: EA; AEC Category: Q200
signal-integrity model Resistor
simulation model Resistor
footprint 0603
footprint 0603M
footprint 0603L
footprint 0603_HV
footprint 0603S
pins: 1, 2

## CRM0805-JW-1R0ELF
designator R?  ValueDisplayed: 1.0  (hidden comment: CRM0805-JW-1R0ELF)
RES, 1.0, 5%, 0.25 W, 0805; Manufacturer: Bourns; CompType: Resistor; Value: 1.0; Res_ohm: 1; Value_Code: 1R00; Tolerance_%: 5; Power_W: 0.25; Value2: 0.25W; VDC_V: 0; TempCo: 100 ppm/C; SizeArea_mm2: 2.5; SizeX_mm: 2; SizeY_mm: 1.25; SizeZ_mm: 1.45; EIA_Code: E24; U/M: EA; AEC Category: Q200
signal-integrity model Resistor
simulation model Resistor
footprint 0805_HV
footprint 0805_HV1
footprint 0805
footprint 0805M
footprint 0805L
pins: 1, 2

## CSD17578Q3A
designator Q?
MOSFET, N-CH, 30 V, 14 A, DNH0008A (VSONP-8); Manufacturer: Texas Instruments; Alternate Manufacturer: None; U/M: EA; ChType: N; Value: 30V; VdsMax_V: 30; Value1: 0.0082 ohm; Rdson45_ohm: 0.0082; Value2: 7.9 nC; QgTyp_nC: 7.9; Vgs_V: 20; IdsMax_A: 14; SizeAreaWB_mm2: 18.49; SizeArea_mm2: 10.89; SizeX_mm: 3.3; SizeZ_mm: 0.9; AEC Category: Q101
footprint DNH0008A
footprint DNH0008A_NV
pins: 1 S, 2 S, 3 S, 4 G, 5 D, 6 D, 7 D, 8 D, 9 D

## CSFMT108-HF
designator D_Aux?
Diode, Superfast Rectifier, 600 V, 1 A, 3.5x1.6mm; Manufacturer: Comchip Technology; U/M: EA; Vf_V: 1.7; Value: 600V; Value1: 1A; Value2: 1.7V; Io_A: 1; Vr_V: 600; TJmax_C: 150; SizeAreaWB_mm2: 11.7; SizeArea_mm2: 5.6; SizeX_mm: 3.5; SizeY_mm: 1.6; AEC Category: Q101; AEC Qualified: N
signal-integrity model Diode
footprint SOD-123H
pins: 1 K, 2 A

## CSR1206FKR300
designator R?  ValueDisplayed: 0.3  (hidden comment: CSR1206FKR300)
RES, 0.3, 1%, 0.5 W, 1206; Manufacturer: Stackpole Electronics Inc; CompType: Resistor; Value: 0.3; Tolerance_%: 1; Value2: 0.5W; TempCo: 100 ppm/C; SizeArea_mm2: 5.12; SizeX_mm: 3.2; SizeY_mm: 1.6; SizeZ_mm: 1.35; U/M: EA; AEC Category: Q200; Value_Code: R300; Power_W: 0.5; EIA_Code: E96
signal-integrity model Resistor
simulation model Resistor
footprint 1206
footprint 1206M
footprint 1206L
pins: 1, 2

## CZRU52C5V6
designator D?  value 6.2V
Diode, Zener, 5.6 V, 150 mW, SOD-523F; Manufacturer: Comchip Technology; SymbolCreator: a0412235; U/M: EA; Power_W: 0.15; Vz_V: 5.6; Value1: 0.15W; SizeAreaWB_mm2: 5.13; SizeArea_mm2: 1.53; SizeX_mm: 1.7; SizeY_mm: 0.9; SizeZ_mm: 0.85; AEC Category: Q101
signal-integrity model Diode
footprint SOD-523F
pins: 1 K, 2 A

## DMP3099L-7
designator Q?, comment DMP510DL
MOSFET, P-CH, -30 V, -3.8 A, AEC-Q101, SOT-23; PartNumber: DMP3099L-7; Manufacturer: Diodes Inc.; Alternate Manufacturer: None; U/M: EA; ChType: P; Value: -30V; Value1: ? ohm; Value2: 5.2 nC; QgTyp_nC: 5.2; Vgs_V: -20; SizeAreaWB_mm2: 14; SizeArea_mm2: 7.5; SizeX_mm: 2.5; SizeY_mm: 3; SizeZ_mm: 1.1; AEC Category: Q101; AEC Qualified: Y
footprint SOT-23
footprint SOT-23M
footprint SOT-23L
pins: 1 G, 2 S, 3 D

## ECA-1HHG100
designator C?  ValueDisplayed: 10µF  (hidden comment: ECA-1HHG100)
CAP, AL, 10 µF, 50 V, +/- 20%, TH; Manufacturer: Panasonic; Polarized: Y; CompType: Capacitor; Value: 10uF; U/M: EA; Cap_F: 0.00001; Tolerance_%: 20; Value1: Unknown; VDC_V: 50; Value2: 50V; IRMS_A: 0.039; TaMin_C: -55; TaMax_C: 105; Cap_Case: 5x11mm; SizeArea_mm2: 25; SizeAreaWB_mm2: 49; SizeX_mm: 5; SizeZ_mm: 12; AEC Category: Q200; AEC Qualified: N
signal-integrity model Cap
simulation model Cap
footprint NHG_500x1100
pins: 1 +, 2 -

## EEE-FK1E471P
designator C?  ValueDisplayed: 470µF  (hidden comment: EEE-FK1E471P)
CAP, AL, 470 µF, 25 V, +/- 20%, 0.08 ohm, AEC-Q200 Grade 2, SMD; Manufacturer: Panasonic; Polarized: Y; CompType: Capacitor; Value: 470uF; U/M: EA; Cap_F: 0.00047; Tolerance_%: 20; VDC_V: 25; Value2: 25V; ESR_ohm: 0.08; IRMS_A: 0.85; TaMin_C: -55; TaMax_C: 105; Cap_Case: G; SizeAreaWB_mm2: 172.2; SizeArea_mm2: 123.6; SizeX_mm: 12; SizeY_mm: 10.3; SizeZ_mm: 10.2; AEC Category: Q200; AEC Grade: 2
signal-integrity model Cap
simulation model Cap
footprint SM_RADIAL_G
pins: 1 +, 2 -

## ERA-3YEB302V
designator R?  ValueDisplayed: 3.00k  (hidden comment: ERA-3YEB302V)
RES, 3.00 k, 0.1%, 0.1 W, 0603; Manufacturer: Panasonic; CompType: Resistor; Value: 3.00k; Res_ohm: 3000; Value_Code: 3k00; Tolerance_%: 0.1; Value2: 0.1W; VDC_V: 75; TempCo: 25 ppm/C; SizeArea_mm2: 1.28; SizeX_mm: 1.6; SizeY_mm: 0.8; SizeZ_mm: 1; U/M: EA; AEC Category: Q200
signal-integrity model Resistor
simulation model Resistor
footprint 0603
footprint 0603M
footprint 0603L
footprint 0603_HV
footprint 0603S
pins: 1, 2

## ERJ-6GEYJ184V
designator R?  ValueDisplayed: 180k  (hidden comment: ERJ-6GEYJ184V)
RES, 180 k, 5%, 0.125 W, 0805; Manufacturer: Panasonic; CompType: Resistor; Value: 180k; Res_ohm: 180000; Tolerance_%: 5; Power_W: 0.125; Value2: 0.125W; VDC_V: 150; TempCo: 200 ppm/C; SizeArea_mm2: 2.5; SizeX_mm: 2; SizeY_mm: 1.25; SizeZ_mm: 1.45; EIA_Code: E24; U/M: EA; AEC Category: Q200
signal-integrity model Resistor
simulation model Resistor
footprint 0805_HV
footprint 0805_HV1
footprint 0805
footprint 0805M
footprint 0805L
pins: 1, 2

## ERJ-6GEYJ220V
designator R?  ValueDisplayed: 22  (hidden comment: ERJ-6GEYJ220V)
RES, 22, 5%, 0.125 W, 0805; Manufacturer: Panasonic; CompType: Resistor; Value: 22; Value_Code: 22R0; Tolerance_%: 5; Power_W: 0.125; Value2: 0.125W; VDC_V: 150; TempCo: 200 ppm/C; SizeArea_mm2: 2.5; SizeX_mm: 2; SizeY_mm: 1.25; SizeZ_mm: 1.45; EIA_Code: E24; U/M: EA; AEC Category: Q200
signal-integrity model Resistor
simulation model Resistor
footprint 0805_HV
footprint 0805_HV1
footprint 0805
footprint 0805M
footprint 0805L
pins: 1, 2

## ESD_Susceptible
designator Logo?, comment ESD Susceptible  (value not drawn)  (no BOM)
ESD Susceptible Symbol; SymbolCreator: a0412235
footprint ESD_Overlay_Large
footprint ESD_Overlay_Medium
footprint ESD_Overlay_Small

## FCC_disclaimer
designator Logo?, comment FCC disclaimer  (no BOM)
FCC_disclaimer; SymbolCreator: codlsc
footprint FCC_disclaimer
footprint FCC_disclaimer_stacked

## Fiducial
designator FID?  (value not drawn)
Fiducial mark.  There is nothing to buy or mount.; SymbolCreator: codlsc
footprint Fiducial10-30
footprint Fiducial10-20
footprint Fiducial15-30
footprint Fiducial20-40
footprint Fiducial6.4-20

## GCM155R71H103KA55D
designator C?  ValueDisplayed: 0.01µF  (hidden comment: GCM155R71H103KA55D)
CAP, CERM, 0.01 µF, 50 V, +/- 10%, C0G/NP0, 0402; Manufacturer: MuRata; Polarized: N; CompType: Capacitor; Value: 0.01uF; U/M: EA; Cap_F: 0.00000001; Tolerance_%: 10; Value1: Unknown; VDC_V: 50; Value2: 50V; TaMin_C: -55; TaMax_C: 125; Cap_Case: 0402; SizeArea_mm2: 0.5; SizeAreaWB_mm2: 3; SizeX_mm: 1; SizeZ_mm: 0.6; AEC Category: Q200
signal-integrity model Cap
simulation model Cap
footprint 0402
footprint 0402M
footprint 0402L
footprint 0402S
pins: 1, 2

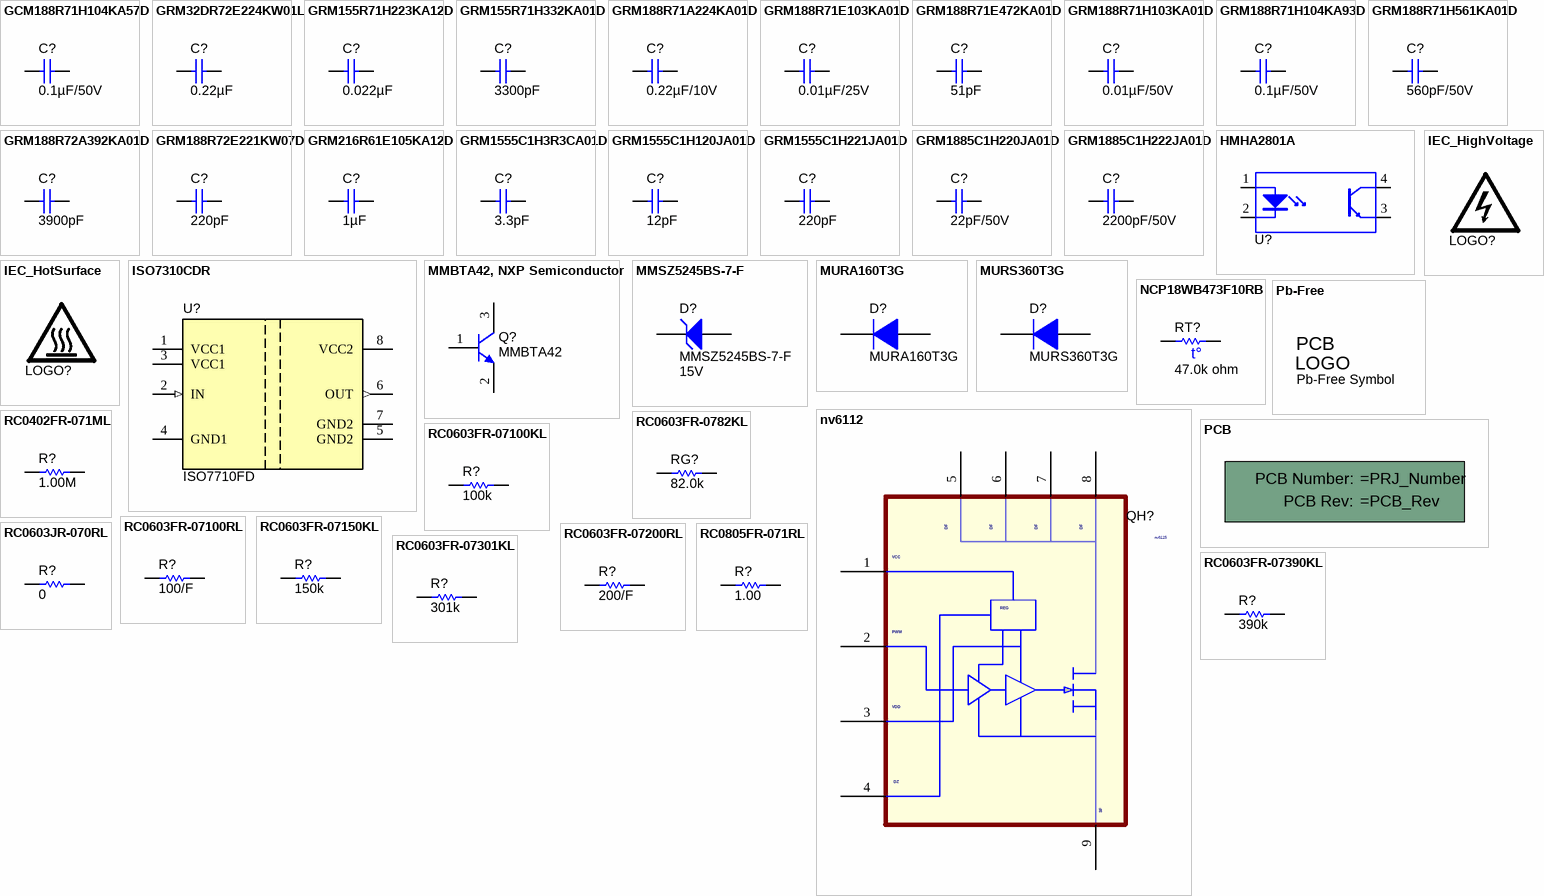
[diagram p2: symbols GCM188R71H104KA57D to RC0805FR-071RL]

## GCM188R71H104KA57D
designator C?  ValueDisplayed: 0.1µF/50V  (hidden comment: GCM188R71H104KA57D)
CAP, CERM, 0.1 µF, 50 V, +/- 10%, X7R, 0603; Manufacturer: MuRata; Polarized: N; CompType: Capacitor; Value: 0.1uF; U/M: EA; Cap_F: 0.0000001; Tolerance_%: 10; ESR_ohm: 0.02; Value1: 0.02 ohm; VDC_V: 50; Value2: 50V; IRMS_A: 1.84; TaMin_C: -55; TaMax_C: 125; Cap_Case: 0603; SizeArea_mm2: 1.28; SizeAreaWB_mm2: 4.68; SizeX_mm: 1.6; SizeY_mm: 0.8; SizeZ_mm: 1; AEC Category: Q200
signal-integrity model Cap
simulation model Cap
footprint 0603
footprint 0603M
footprint 0603L
footprint 0603_HV
footprint 0603S
pins: 1, 2

## GRM32DR72E224KW01L
designator C?  ValueDisplayed: 0.22µF  (hidden comment: GRM32DR72E224KW01L)
CAP, CERM, 0.22 µF, 250 V, +/- 10%, X7R, 1210; Manufacturer: MuRata; Polarized: N; CompType: Capacitor; Value: 0.22uF; U/M: EA; Cap_F: 0.00000022; Tolerance_%: 10; Value1: Unknown; VDC_V: 250; Value2: 250V; TaMin_C: -55; TaMax_C: 125; Cap_Case: 1210; SizeArea_mm2: 8; SizeAreaWB_mm2: 14.7; SizeX_mm: 3.2; SizeY_mm: 2.5; SizeZ_mm: 2.2; AEC Category: Q200
signal-integrity model Cap
simulation model Cap
footprint 1210_220
footprint 1210_220M
footprint 1210_220L
pins: 1, 2

## GRM155R71H223KA12D
designator C?  ValueDisplayed: 0.022µF  (hidden comment: GRM155R71H223KA12D)
CAP, CERM, 0.022 µF, 50 V, +/- 10%, X7R, 0402; Manufacturer: MuRata; Polarized: N; CompType: Capacitor; Value: 0.022uF; U/M: EA; Cap_F: 0.000000022; Tolerance_%: 10; Value1: Unknown; VDC_V: 50; Value2: 50V; TaMin_C: -55; TaMax_C: 125; Cap_Case: 0402; SizeArea_mm2: 0.5; SizeAreaWB_mm2: 3; SizeX_mm: 1; SizeZ_mm: 0.6; AEC Category: Q200
signal-integrity model Cap
simulation model Cap
footprint 0402
footprint 0402M
footprint 0402L
footprint 0402S
pins: 1, 2

## GRM155R71H332KA01D
designator C?  ValueDisplayed: 3300pF  (hidden comment: GRM155R71H332KA01D)
CAP, CERM, 3300 pF, 50 V, +/- 10%, X7R, 0402; Manufacturer: MuRata; Polarized: N; CompType: Capacitor; Value: 3300pF; U/M: EA; Cap_F: 0.0000000033; Tolerance_%: 10; Value1: Unknown; VDC_V: 50; Value2: 50V; TaMin_C: -55; TaMax_C: 125; Cap_Case: 0402; SizeArea_mm2: 0.5; SizeAreaWB_mm2: 3; SizeX_mm: 1; SizeZ_mm: 0.6; AEC Category: Q200
signal-integrity model Cap
simulation model Cap
footprint 0402
footprint 0402M
footprint 0402L
footprint 0402S
pins: 1, 2

## GRM188R71A224KA01D
designator C?  ValueDisplayed: 0.22µF/10V  (hidden comment: GRM188R71A224KA01D)
CAP, CERM, 0.22 µF, 10 V, +/- 10%, X7R, 0603; Manufacturer: MuRata; Polarized: N; CompType: Capacitor; Value: 0.22uF; U/M: EA; Cap_F: 0.00000022; Tolerance_%: 10; Value1: Unknown; Value2: 10V; TaMin_C: -55; TaMax_C: 125; Cap_Case: 0603; SizeArea_mm2: 1.28; SizeAreaWB_mm2: 4.68; SizeX_mm: 1.6; SizeY_mm: 0.8; SizeZ_mm: 1; AEC Category: Q200
signal-integrity model Cap
simulation model Cap
footprint 0603
footprint 0603M
footprint 0603L
footprint 0603_HV
footprint 0603S
pins: 1, 2

## GRM188R71E103KA01D
designator C?  ValueDisplayed: 0.01µF/25V  (hidden comment: GRM188R71E103KA01D)
CAP, CERM, 0.01 µF, 25 V, +/- 10%, X7R, 0603; Manufacturer: MuRata; Polarized: N; CompType: Capacitor; Value: 0.01uF; U/M: EA; Cap_F: 0.00000001; Tolerance_%: 10; Value1: Unknown; VDC_V: 25; Value2: 25V; TaMin_C: -55; TaMax_C: 125; Cap_Case: 0603; SizeArea_mm2: 1.28; SizeAreaWB_mm2: 4.68; SizeX_mm: 1.6; SizeY_mm: 0.8; SizeZ_mm: 1; AEC Category: Q200
signal-integrity model Cap
simulation model Cap
footprint 0603
footprint 0603M
footprint 0603L
footprint 0603_HV
footprint 0603S
pins: 1, 2

## GRM188R71E472KA01D
designator C?  ValueDisplayed: 51pF  (hidden comment: GRM188R71E472KA01D)
CAP, CERM, 51 pF, 50 V,+/- 5%, C0G/NP0, 0603; Manufacturer: MuRata; Polarized: N; CompType: Capacitor; Value: 51pF; U/M: EA; Cap_F: 0.0000000047; Tolerance_%: 10; VDC_V: 50; Value2: 50V; TempCo: X7R; TaMin_C: -55; TaMax_C: 125; Cap_Case: 0603; SizeArea_mm2: 1.28; SizeAreaWB_mm2: 4.68; SizeX_mm: 1.6; SizeY_mm: 0.8; SizeZ_mm: 1; AEC Category: Q200
signal-integrity model Cap
simulation model Cap
footprint 0603
footprint 0603M
footprint 0603L
footprint 0603_HV
footprint 0603S
pins: 1, 2

## GRM188R71H103KA01D
designator C?  ValueDisplayed: 0.01µF/50V  (hidden comment: GRM188R71H103KA01D)
CAP, CERM, 0.01 µF, 50 V, +/- 10%, X7R, 0603; Manufacturer: MuRata; Polarized: N; CompType: Capacitor; Value: 0.01uF; U/M: EA; Cap_F: 0.00000001; Tolerance_%: 10; Value1: Unknown; VDC_V: 50; Value2: 50V; TaMin_C: -55; TaMax_C: 125; Cap_Case: 0603; SizeArea_mm2: 1.28; SizeAreaWB_mm2: 4.68; SizeX_mm: 1.6; SizeY_mm: 0.8; SizeZ_mm: 1; AEC Category: Q200
signal-integrity model Cap
simulation model Cap
footprint 0603
footprint 0603M
footprint 0603L
footprint 0603_HV
footprint 0603S
pins: 1, 2

## GRM188R71H104KA93D
designator C?  ValueDisplayed: 0.1µF/50V  (hidden comment: GRM188R71H104KA93D)
CAP, CERM, 0.1 µF, 50 V, +/- 10%, X7R, 0603; Manufacturer: MuRata; Polarized: N; CompType: Capacitor; Value: 0.1uF; U/M: EA; Cap_F: 0.0000001; Tolerance_%: 10; Value1: Unknown; VDC_V: 50; Value2: 50V; TaMin_C: -55; TaMax_C: 125; Cap_Case: 0603; SizeArea_mm2: 1.28; SizeAreaWB_mm2: 4.68; SizeX_mm: 1.6; SizeY_mm: 0.8; SizeZ_mm: 1; AEC Category: Q200
signal-integrity model Cap
simulation model Cap
footprint 0603
footprint 0603M
footprint 0603L
footprint 0603_HV
footprint 0603S
pins: 1, 2

## GRM188R71H561KA01D
designator C?  ValueDisplayed: 560pF/50V  (hidden comment: GRM188R71H561KA01D)
CAP, CERM, 560 pF, 50 V, +/- 10%, X7R, 0603; Manufacturer: MuRata; Polarized: N; CompType: Capacitor; Value: 560pF; U/M: EA; Cap_F: 0.00000000056; Tolerance_%: 10; Value1: Unknown; VDC_V: 50; Value2: 50V; TaMin_C: -55; TaMax_C: 125; Cap_Case: 0603; SizeArea_mm2: 1.28; SizeAreaWB_mm2: 4.68; SizeX_mm: 1.6; SizeY_mm: 0.8; SizeZ_mm: 1; AEC Category: Q200
signal-integrity model Cap
simulation model Cap
footprint 0603
footprint 0603M
footprint 0603L
footprint 0603_HV
footprint 0603S
pins: 1, 2

## GRM188R72A392KA01D
designator C?  ValueDisplayed: 3900pF  (hidden comment: GRM188R72A392KA01D)
CAP, CERM, 3900 pF, 100 V,+/- 10%, X7R, 0603; Manufacturer: MuRata; Polarized: N; CompType: Capacitor; Value: 3900pF; U/M: EA; Cap_F: 0.0000000039; Tolerance_%: 10; VDC_V: 100; Value2: 100V; TaMin_C: -55; TaMax_C: 125; Cap_Case: 0603; SizeArea_mm2: 1.28; SizeAreaWB_mm2: 4.68; SizeX_mm: 1.6; SizeY_mm: 0.8; SizeZ_mm: 1; AEC Category: Q200
signal-integrity model Cap
simulation model Cap
footprint 0603
footprint 0603M
footprint 0603L
footprint 0603_HV
footprint 0603S
pins: 1, 2

## GRM188R72E221KW07D
designator C?  ValueDisplayed: 220pF  (hidden comment: GRM188R72E221KW07D)
CAP, CERM, 220 pF, 250 V, +/- 10%, X7R, 0603; Manufacturer: MuRata; Polarized: N; CompType: Capacitor; Value: 220pF; U/M: EA; Cap_F: 0.00000000022; Tolerance_%: 10; Value1: Unknown; VDC_V: 250; Value2: 250V; TaMin_C: -55; TaMax_C: 125; Cap_Case: 0603; SizeArea_mm2: 1.28; SizeAreaWB_mm2: 4.68; SizeX_mm: 1.6; SizeY_mm: 0.8; SizeZ_mm: 1; AEC Category: Q200
signal-integrity model Cap
simulation model Cap
footprint 0603
footprint 0603M
footprint 0603L
footprint 0603_HV
footprint 0603S
pins: 1, 2

## GRM216R61E105KA12D
designator C?  ValueDisplayed: 1µF  (hidden comment: GRM216R61E105KA12D)
CAP, CERM, 1 µF, 25 V,+/- 10%, X5R, 0805; Manufacturer: MuRata; Polarized: N; CompType: Capacitor; Value: 1uF; U/M: EA; Cap_F: 0.000001; Tolerance_%: 10; ESR_ohm: 0.009; Value1: 0.009 ohm; VDC_V: 25; Value2: 25V; TaMin_C: -55; TaMax_C: 85; Cap_Case: 0805; SizeArea_mm2: 2.5; SizeAreaWB_mm2: 6.75; SizeX_mm: 2; SizeY_mm: 1.25; SizeZ_mm: 1.45; AEC Category: Q200; Green_Lifecycle: Active; Green_REACh: Passed
signal-integrity model Cap
simulation model Cap
footprint 0805_HV
footprint 0805_HV1
footprint 0805
footprint 0805M
footprint 0805L
pins: 1, 2

## GRM1555C1H3R3CA01D
designator C?  ValueDisplayed: 3.3pF  (hidden comment: GRM1555C1H3R3CA01D)
CAP, CERM, 3.3 pF, 50 V, +/- 5%, C0G/NP0, 0402; Manufacturer: MuRata; Polarized: N; CompType: Capacitor; Value: 3.3pF; U/M: EA; Cap_F: 0.0000000000033; Tolerance_%: 5; Value1: Unknown; VDC_V: 50; Value2: 50V; TaMin_C: -55; TaMax_C: 125; Cap_Case: 0402; SizeArea_mm2: 0.5; SizeAreaWB_mm2: 3; SizeX_mm: 1; SizeZ_mm: 0.6; AEC Category: Q200
signal-integrity model Cap
simulation model Cap
footprint 0402
footprint 0402M
footprint 0402L
footprint 0402S
pins: 1, 2

## GRM1555C1H120JA01D
designator C?  ValueDisplayed: 12pF  (hidden comment: GRM1555C1H120JA01D)
CAP, CERM, 12 pF, 50 V, +/- 5%, C0G/NP0, 0402; Manufacturer: MuRata; Polarized: N; CompType: Capacitor; Value: 12pF; U/M: EA; Cap_F: 0.000000000012; Tolerance_%: 5; Value1: Unknown; VDC_V: 50; Value2: 50V; TaMin_C: -55; TaMax_C: 125; Cap_Case: 0402; SizeArea_mm2: 0.5; SizeAreaWB_mm2: 3; SizeX_mm: 1; SizeZ_mm: 0.6; AEC Category: Q200
signal-integrity model Cap
simulation model Cap
footprint 0402
footprint 0402M
footprint 0402L
footprint 0402S
pins: 1, 2

## GRM1555C1H221JA01D
designator C?  ValueDisplayed: 220pF  (hidden comment: GRM1555C1H221JA01D)
CAP, CERM, 220 pF, 50 V, +/- 5%, C0G/NP0, 0402; Manufacturer: MuRata; Polarized: N; CompType: Capacitor; Value: 220pF; U/M: EA; Cap_F: 0.00000000022; Tolerance_%: 5; Value1: Unknown; VDC_V: 50; Value2: 50V; TaMin_C: -55; TaMax_C: 125; Cap_Case: 0402; SizeArea_mm2: 0.5; SizeAreaWB_mm2: 3; SizeX_mm: 1; SizeZ_mm: 0.6; AEC Category: Q200
signal-integrity model Cap
simulation model Cap
footprint 0402
footprint 0402M
footprint 0402L
footprint 0402S
pins: 1, 2

## GRM1885C1H220JA01D
designator C?  ValueDisplayed: 22pF/50V  (hidden comment: GRM1885C1H220JA01D)
CAP, CERM, 22 pF, 50 V, +/- 5%, C0G/NP0, 0603; Manufacturer: MuRata; Polarized: N; CompType: Capacitor; Value: 22pF; U/M: EA; Cap_F: 0.000000000022; Tolerance_%: 5; Value1: Unknown; VDC_V: 50; Value2: 50V; TaMin_C: -55; TaMax_C: 125; Cap_Case: 0603; SizeArea_mm2: 1.28; SizeAreaWB_mm2: 4.68; SizeX_mm: 1.6; SizeY_mm: 0.8; SizeZ_mm: 1; AEC Category: Q200
signal-integrity model Cap
simulation model Cap
footprint 0603
footprint 0603M
footprint 0603L
footprint 0603_HV
footprint 0603S
pins: 1, 2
